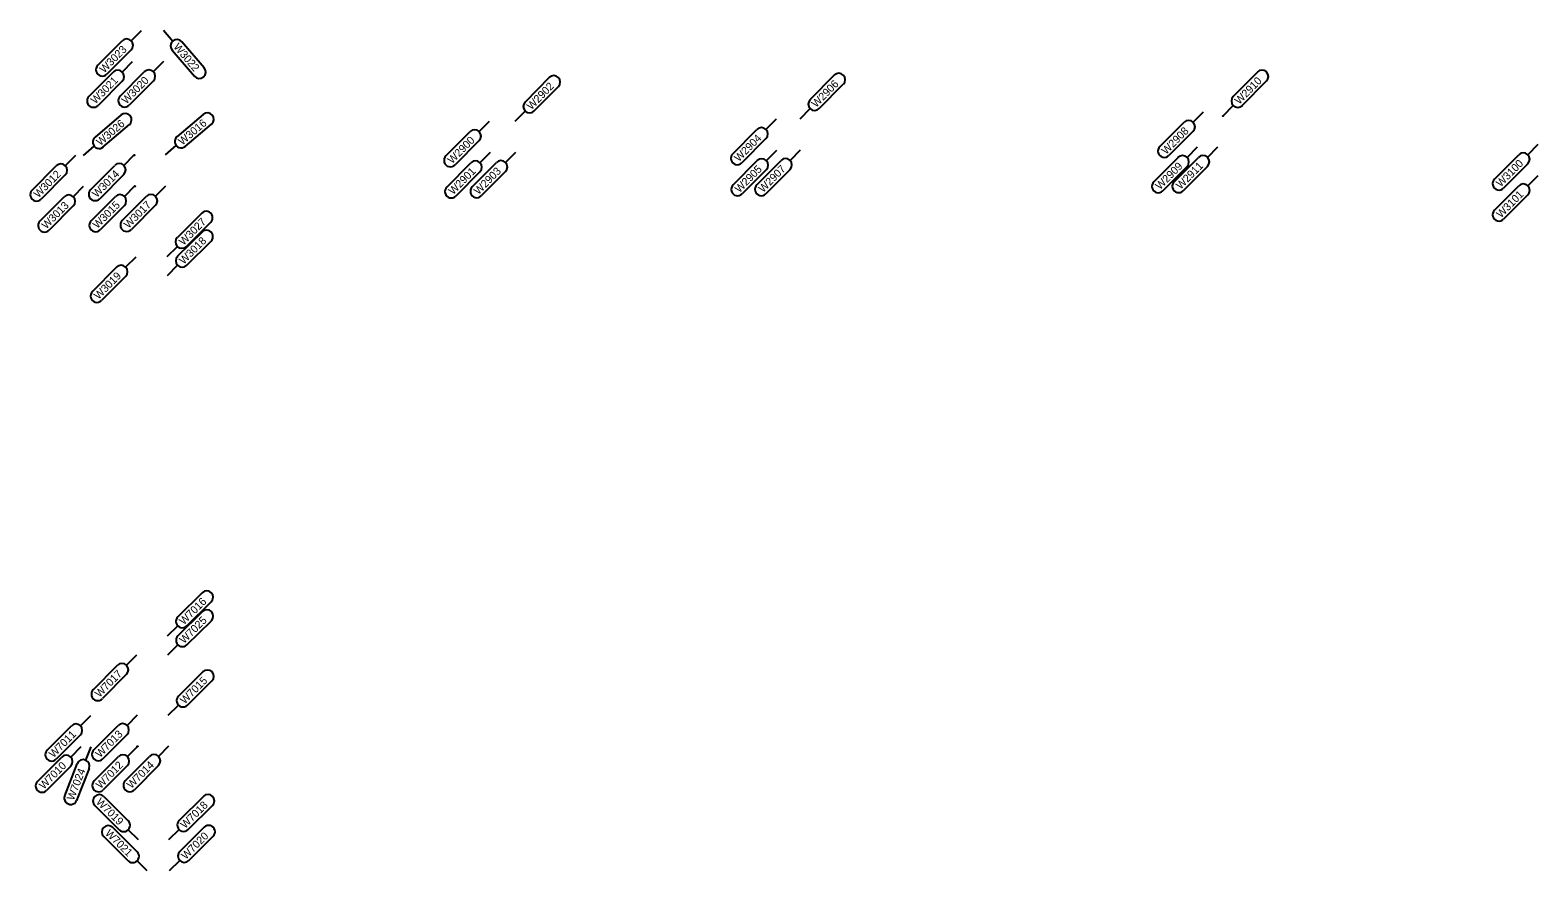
# Model space of a CAD drawing. Extents: x 12479652 to 12487250, y 9842710 to 9846560.
# Drawn here: x 12485106.7 to 12485348.9, y 9842745.8 to 9842880.8 of the extents above; entities that cross this region are included whole.
import ezdxf

# ---------------------------------------------------------------- set-up
doc = ezdxf.new("R2010")
doc.units = 0
doc.layers.add('_CIVIL_CONSTRUCTION', color=7, linetype='Continuous')
doc.layers.add('TextAlignmentLrg', color=7, linetype='Continuous')

msp = doc.modelspace()

# ---------------------------------------------------------------- linework, layer by layer
at = {"layer": '_CIVIL_CONSTRUCTION'}
for p, q in [((12485124.54, 9842880.74), (12485122.92, 9842879.11)), ((12485128.13, 9842880.82), (12485129.62, 9842879.07)), ((12485117.58, 9842875.2), (12485121.47, 9842879.11)), ((12485122.92, 9842877.66), (12485119.03, 9842873.75)), ((12485129.5, 9842877.63), (12485133.08, 9842873.43)), ((12485134.65, 9842874.76), (12485131.06, 9842878.96)), ((12485123.1, 9842875.73), (12485121.48, 9842874.1)), ((12485128.1, 9842875.77), (12485126.48, 9842874.14)), ((12485116.14, 9842870.18), (12485120.03, 9842874.1)), ((12485121.49, 9842872.65), (12485117.6, 9842868.74)), ((12485121.14, 9842870.22), (12485125.03, 9842874.13)), ((12485126.49, 9842872.69), (12485122.6, 9842868.78)), ((12485190.1, 9842873.21), (12485186.22, 9842869.28)), ((12485235.89, 9842873.59), (12485232.01, 9842869.67)), ((12485303.88, 9842874.1), (12485300, 9842870.17)), ((12485301.46, 9842868.73), (12485305.34, 9842872.66)), ((12485187.69, 9842867.84), (12485191.56, 9842871.77)), ((12485233.47, 9842868.23), (12485237.35, 9842872.15)), ((12485184.62, 9842866.19), (12485186.23, 9842867.83)), ((12485230.41, 9842866.58), (12485232.02, 9842868.22)), ((12485298.4, 9842867.08), (12485300.01, 9842868.72)), ((12485121.31, 9842867.2), (12485117.11, 9842863.62)), ((12485118.44, 9842862.06), (12485122.64, 9842865.64)), ((12485134.48, 9842867.29), (12485130.28, 9842863.71)), ((12485131.61, 9842862.15), (12485135.81, 9842865.73)), ((12485180.46, 9842866.16), (12485178.84, 9842864.53)), ((12485226.54, 9842866.5), (12485224.92, 9842864.87)), ((12485288.22, 9842862.11), (12485292.11, 9842866.03)), ((12485295.18, 9842867.66), (12485293.56, 9842866.03)), ((12485173.5, 9842860.61), (12485177.39, 9842864.52)), ((12485178.85, 9842863.08), (12485174.96, 9842859.16)), ((12485219.58, 9842860.95), (12485223.47, 9842864.86)), ((12485224.92, 9842863.42), (12485221.03, 9842859.5)), ((12485293.56, 9842864.58), (12485289.67, 9842860.67)), ((12485113.95, 9842860.67), (12485112.33, 9842859.03)), ((12485115.25, 9842860.68), (12485117, 9842862.17)), ((12485123.37, 9842860.74), (12485121.74, 9842859.1)), ((12485128.42, 9842860.77), (12485130.17, 9842862.27)), ((12485180.59, 9842861.16), (12485178.96, 9842859.53)), ((12485184.69, 9842861.19), (12485183.07, 9842859.56)), ((12485226.6, 9842861.5), (12485224.98, 9842859.87)), ((12485230.42, 9842861.53), (12485228.79, 9842859.9)), ((12485294.2, 9842862), (12485292.58, 9842860.37)), ((12485297.47, 9842862.02), (12485295.85, 9842860.39)), ((12485341.98, 9842856.89), (12485345.87, 9842860.8)), ((12485348.94, 9842862.44), (12485347.32, 9842860.81)), ((12485106.99, 9842855.12), (12485110.88, 9842859.03)), ((12485116.4, 9842855.19), (12485120.29, 9842859.1)), ((12485173.62, 9842855.61), (12485177.51, 9842859.52)), ((12485177.73, 9842855.64), (12485181.62, 9842859.55)), ((12485219.64, 9842855.95), (12485223.53, 9842859.86)), ((12485224.98, 9842858.42), (12485221.09, 9842854.5)), ((12485223.45, 9842855.98), (12485227.34, 9842859.89)), ((12485228.8, 9842858.44), (12485224.91, 9842854.53)), ((12485287.24, 9842856.45), (12485291.13, 9842860.36)), ((12485292.58, 9842858.92), (12485288.69, 9842855)), ((12485290.51, 9842856.47), (12485294.4, 9842860.39)), ((12485295.86, 9842858.94), (12485291.97, 9842855.03)), ((12485347.33, 9842859.36), (12485343.44, 9842855.44)), ((12485112.33, 9842857.58), (12485108.44, 9842853.67)), ((12485121.75, 9842857.65), (12485117.86, 9842853.74)), ((12485123.45, 9842855.74), (12485121.83, 9842854.1)), ((12485128.45, 9842855.77), (12485126.83, 9842854.14)), ((12485178.97, 9842858.08), (12485175.08, 9842854.16)), ((12485183.07, 9842858.11), (12485179.18, 9842854.19)), ((12485341.98, 9842851.89), (12485345.87, 9842855.8)), ((12485348.94, 9842857.44), (12485347.32, 9842855.81)), ((12485108.27, 9842850.13), (12485112.16, 9842854.04)), ((12485115.23, 9842855.68), (12485113.61, 9842854.04)), ((12485116.49, 9842850.19), (12485120.38, 9842854.1)), ((12485121.49, 9842850.22), (12485125.38, 9842854.14)), ((12485347.33, 9842854.36), (12485343.44, 9842850.44)), ((12485113.61, 9842852.59), (12485109.72, 9842848.68)), ((12485121.84, 9842852.65), (12485117.95, 9842848.74)), ((12485126.84, 9842852.69), (12485122.95, 9842848.78)), ((12485134.25, 9842851.42), (12485130.34, 9842847.53)), ((12485131.79, 9842846.07), (12485135.7, 9842849.96)), ((12485128.7, 9842844.46), (12485130.34, 9842846.08)), ((12485134.31, 9842848.39), (12485130.39, 9842844.5)), ((12485131.84, 9842843.04), (12485135.75, 9842846.93)), ((12485123.65, 9842844.37), (12485122.03, 9842842.74)), ((12485116.69, 9842838.82), (12485120.58, 9842842.73)), ((12485122.04, 9842841.29), (12485118.15, 9842837.37)), ((12485128.76, 9842841.43), (12485130.39, 9842843.05)), ((12485134.34, 9842790.44), (12485130.41, 9842786.56)), ((12485131.85, 9842785.1), (12485135.78, 9842788.98)), ((12485134.36, 9842787.4), (12485130.44, 9842783.53)), ((12485131.88, 9842782.07), (12485135.81, 9842785.94)), ((12485128.76, 9842783.49), (12485130.4, 9842785.11)), ((12485128.79, 9842780.46), (12485130.43, 9842782.08)), ((12485116.83, 9842774.86), (12485120.72, 9842778.78)), ((12485123.79, 9842780.41), (12485122.17, 9842778.78)), ((12485122.18, 9842777.33), (12485118.29, 9842773.42)), ((12485134.46, 9842777.72), (12485130.53, 9842773.84)), ((12485131.98, 9842772.38), (12485135.9, 9842776.26)), ((12485128.89, 9842770.78), (12485130.52, 9842772.39)), ((12485109.42, 9842765.13), (12485113.31, 9842769.05)), ((12485116.38, 9842770.68), (12485114.76, 9842769.05)), ((12485116.93, 9842765.19), (12485120.82, 9842769.1)), ((12485123.89, 9842770.74), (12485122.27, 9842769.11)), ((12485114.76, 9842767.6), (12485110.87, 9842763.69)), ((12485122.27, 9842767.66), (12485118.38, 9842763.74)), ((12485107.87, 9842760.12), (12485111.76, 9842764.04)), ((12485114.84, 9842765.67), (12485113.21, 9842764.04)), ((12485116.42, 9842765.68), (12485115.58, 9842763.54)), ((12485116.97, 9842760.19), (12485120.86, 9842764.1)), ((12485121.97, 9842760.23), (12485125.86, 9842764.14)), ((12485123.94, 9842765.74), (12485122.32, 9842764.11)), ((12485128.94, 9842765.78), (12485127.32, 9842764.14)), ((12485113.22, 9842762.59), (12485109.33, 9842758.68)), ((12485112.24, 9842757.82), (12485114.25, 9842762.96)), ((12485116.16, 9842762.21), (12485114.15, 9842757.07)), ((12485122.32, 9842762.66), (12485118.43, 9842758.74)), ((12485127.32, 9842762.69), (12485123.43, 9842758.78)), ((12485118.53, 9842757.7), (12485122.45, 9842753.81)), ((12485134.54, 9842757.72), (12485130.62, 9842753.84)), ((12485121, 9842752.36), (12485117.09, 9842756.25)), ((12485132.06, 9842752.38), (12485135.98, 9842756.26)), ((12485119.96, 9842752.71), (12485123.87, 9842748.82)), ((12485124.08, 9842750.74), (12485122.45, 9842752.36)), ((12485128.97, 9842750.78), (12485130.61, 9842752.39)), ((12485134.65, 9842752.76), (12485130.74, 9842748.87)), ((12485122.43, 9842747.37), (12485118.51, 9842751.26)), ((12485132.18, 9842747.41), (12485136.1, 9842751.3)), ((12485125.51, 9842745.75), (12485123.88, 9842747.37)), ((12485129.1, 9842745.8), (12485130.73, 9842747.42))]:
    msp.add_line(p, q, dxfattribs=at)
for centre, start, end in [((12485122.19, 9842878.39), 315.1702, 135.1702), ((12485130.28, 9842878.29), 40.4712, 220.4712), ((12485118.3, 9842874.47), 135.1702, 315.1702), ((12485120.76, 9842873.37), 315.1702, 135.1702), ((12485125.76, 9842873.41), 315.1702, 135.1702), ((12485133.87, 9842874.1), 220.4712, 40.4712), ((12485190.83, 9842872.49), 315.3788, 135.3788), ((12485236.62, 9842872.87), 315.3788, 135.3788), ((12485304.61, 9842873.38), 315.3788, 135.3788), ((12485116.87, 9842869.46), 135.1702, 315.1702), ((12485121.87, 9842869.5), 135.1702, 315.1702), ((12485186.96, 9842868.56), 135.3788, 315.3788), ((12485232.74, 9842868.95), 135.3788, 315.3788), ((12485300.73, 9842869.45), 135.3788, 315.3788), ((12485121.97, 9842866.42), 310.4712, 130.4712), ((12485135.15, 9842866.51), 310.4712, 130.4712), ((12485292.83, 9842865.3), 315.1702, 135.1702), ((12485117.78, 9842862.84), 130.4712, 310.4712), ((12485130.95, 9842862.93), 130.4712, 310.4712), ((12485178.12, 9842863.8), 315.1702, 135.1702), ((12485224.19, 9842864.14), 315.1702, 135.1702), ((12485174.23, 9842859.89), 135.1702, 315.1702), ((12485220.3, 9842860.23), 135.1702, 315.1702), ((12485288.94, 9842861.39), 135.1702, 315.1702), ((12485291.85, 9842859.64), 315.1702, 135.1702), ((12485295.13, 9842859.66), 315.1702, 135.1702), ((12485346.6, 9842860.08), 315.1702, 135.1702), ((12485111.61, 9842858.31), 315.1702, 135.1702), ((12485121.02, 9842858.38), 315.1702, 135.1702), ((12485178.24, 9842858.8), 315.1702, 135.1702), ((12485182.34, 9842858.83), 315.1702, 135.1702), ((12485224.25, 9842859.14), 315.1702, 135.1702), ((12485228.07, 9842859.17), 315.1702, 135.1702), ((12485220.37, 9842855.23), 135.1702, 315.1702), ((12485224.18, 9842855.25), 135.1702, 315.1702), ((12485287.96, 9842855.73), 135.1702, 315.1702), ((12485291.24, 9842855.75), 135.1702, 315.1702), ((12485342.71, 9842856.17), 135.1702, 315.1702), ((12485346.6, 9842855.08), 315.1702, 135.1702), ((12485107.72, 9842854.39), 135.1702, 315.1702), ((12485112.89, 9842853.32), 315.1702, 135.1702), ((12485117.13, 9842854.46), 135.1702, 315.1702), ((12485121.11, 9842853.38), 315.1702, 135.1702), ((12485126.11, 9842853.41), 315.1702, 135.1702), ((12485174.35, 9842854.89), 135.1702, 315.1702), ((12485178.45, 9842854.92), 135.1702, 315.1702), ((12485134.98, 9842850.69), 314.8298, 134.8298), ((12485342.71, 9842851.17), 135.1702, 315.1702), ((12485109, 9842849.4), 135.1702, 315.1702), ((12485117.22, 9842849.46), 135.1702, 315.1702), ((12485122.22, 9842849.5), 135.1702, 315.1702), ((12485135.03, 9842847.66), 314.8298, 134.8298), ((12485131.06, 9842846.8), 134.8298, 314.8298), ((12485131.12, 9842843.77), 134.8298, 314.8298), ((12485121.31, 9842842.01), 315.1702, 135.1702), ((12485117.42, 9842838.1), 135.1702, 315.1702), ((12485135.06, 9842789.71), 314.6453, 134.6453), ((12485131.13, 9842785.83), 134.6453, 314.6453), ((12485135.09, 9842786.67), 314.6453, 134.6453), ((12485131.16, 9842782.8), 134.6453, 314.6453), ((12485121.45, 9842778.05), 315.1702, 135.1702), ((12485135.18, 9842776.99), 314.6453, 134.6453), ((12485117.56, 9842774.14), 135.1702, 315.1702), ((12485131.25, 9842773.11), 134.6453, 314.6453), ((12485114.04, 9842768.32), 315.1702, 135.1702), ((12485121.54, 9842768.38), 315.1702, 135.1702), ((12485110.15, 9842764.41), 135.1702, 315.1702), ((12485112.49, 9842763.31), 315.1702, 135.1702), ((12485117.65, 9842764.47), 135.1702, 315.1702), ((12485121.59, 9842763.38), 315.1702, 135.1702), ((12485126.59, 9842763.42), 315.1702, 135.1702), ((12485115.21, 9842762.59), 338.6455, 158.6455), ((12485108.6, 9842759.4), 135.1702, 315.1702), ((12485117.7, 9842759.47), 135.1702, 315.1702), ((12485122.7, 9842759.5), 135.1702, 315.1702), ((12485113.2, 9842757.45), 158.6455, 338.6455), ((12485117.81, 9842756.97), 45.1702, 225.1702), ((12485135.26, 9842756.99), 314.6453, 134.6453), ((12485119.24, 9842751.99), 45.1702, 225.1702), ((12485121.72, 9842753.09), 225.1702, 45.1702), ((12485131.34, 9842753.11), 134.6453, 314.6453), ((12485135.37, 9842752.03), 314.8298, 134.8298), ((12485123.15, 9842748.1), 225.1702, 45.1702), ((12485131.46, 9842748.14), 134.8298, 314.8298)]:
    msp.add_arc(centre, 1.03, start, end, dxfattribs=at)
at = {"layer": 'TextAlignmentLrg'}
for centre in [(12485298.34, 9842867.03), (12485123.42, 9842860.74), (12485123.51, 9842855.74), (12485123.94, 9842765.74)]:
    msp.add_circle(centre, 0.05, dxfattribs=at)

# ---------------------------------------------------------------- texts
at = {"layer": '_CIVIL_CONSTRUCTION'}
for s, rotation, p in [('W3023', 45.1702, (12485118.58, 9842873.85)), ('W3022', 310.4712, (12485129.63, 9842878.08)), ('W3021', 45.1702, (12485117.18, 9842868.87)), ('W3020', 45.1702, (12485122.14, 9842868.87)), ('W2906', 45.3788, (12485232.99, 9842868.3)), ('W2910', 45.3788, (12485300.98, 9842868.8)), ('W2902', 45.3788, (12485187.23, 9842867.93)), ('W3026', 40.4712, (12485117.97, 9842862.17)), ('W3016', 40.4712, (12485131.14, 9842862.26)), ('W2900', 45.1702, (12485174.5, 9842859.26)), ('W2904', 45.1702, (12485220.57, 9842859.59)), ('W2908', 45.1702, (12485289.22, 9842860.76)), ('W3012', 45.1702, (12485108.01, 9842853.79)), ('W3014', 45.1702, (12485117.4, 9842853.83)), ('W2901', 45.1702, (12485174.66, 9842854.29)), ('W2903', 45.1702, (12485178.73, 9842854.3)), ('W2905', 45.1702, (12485220.65, 9842854.61)), ('W2907', 45.1702, (12485224.46, 9842854.64)), ('W2909', 45.1702, (12485288.24, 9842855.1)), ('W2911', 45.1702, (12485291.55, 9842855.16)), ('W3100', 45.1702, (12485342.98, 9842855.54)), ('W3015', 45.1702, (12485117.5, 9842848.85)), ('W3017', 45.1702, (12485122.5, 9842848.88)), ('W3101', 45.1702, (12485343.02, 9842850.57)), ('W3013', 45.1702, (12485109.28, 9842848.78)), ('W3027', 44.8298, (12485131.32, 9842846.16)), ('W3018', 44.8298, (12485131.36, 9842843.12)), ('W3019', 45.1702, (12485117.69, 9842837.47)), ('W7016', 44.6453, (12485131.37, 9842785.18)), ('W7025', 44.6453, (12485131.42, 9842782.16)), ('W7017', 45.1702, (12485117.84, 9842773.52)), ('W7015', 44.6453, (12485131.51, 9842772.47)), ('W7011', 45.1702, (12485110.45, 9842763.82)), ('W7013', 45.1702, (12485117.93, 9842763.85)), ('W7010', 45.1702, (12485108.87, 9842758.77)), ('W7024', 68.6455, (12485113.69, 9842756.97)), ('W7012', 45.1702, (12485117.99, 9842758.86)), ('W7014', 45.1702, (12485122.97, 9842758.87)), ('W7019', 315.1702, (12485117.18, 9842756.7)), ('W7018', 44.6453, (12485131.58, 9842752.46)), ('W7021', 315.1702, (12485118.65, 9842751.68)), ('W7020', 44.8298, (12485131.7, 9842747.49))]:
    msp.add_text(s, height=1.25, rotation=rotation, dxfattribs=at).set_placement(p)

doc.saveas('drawing.dxf')
